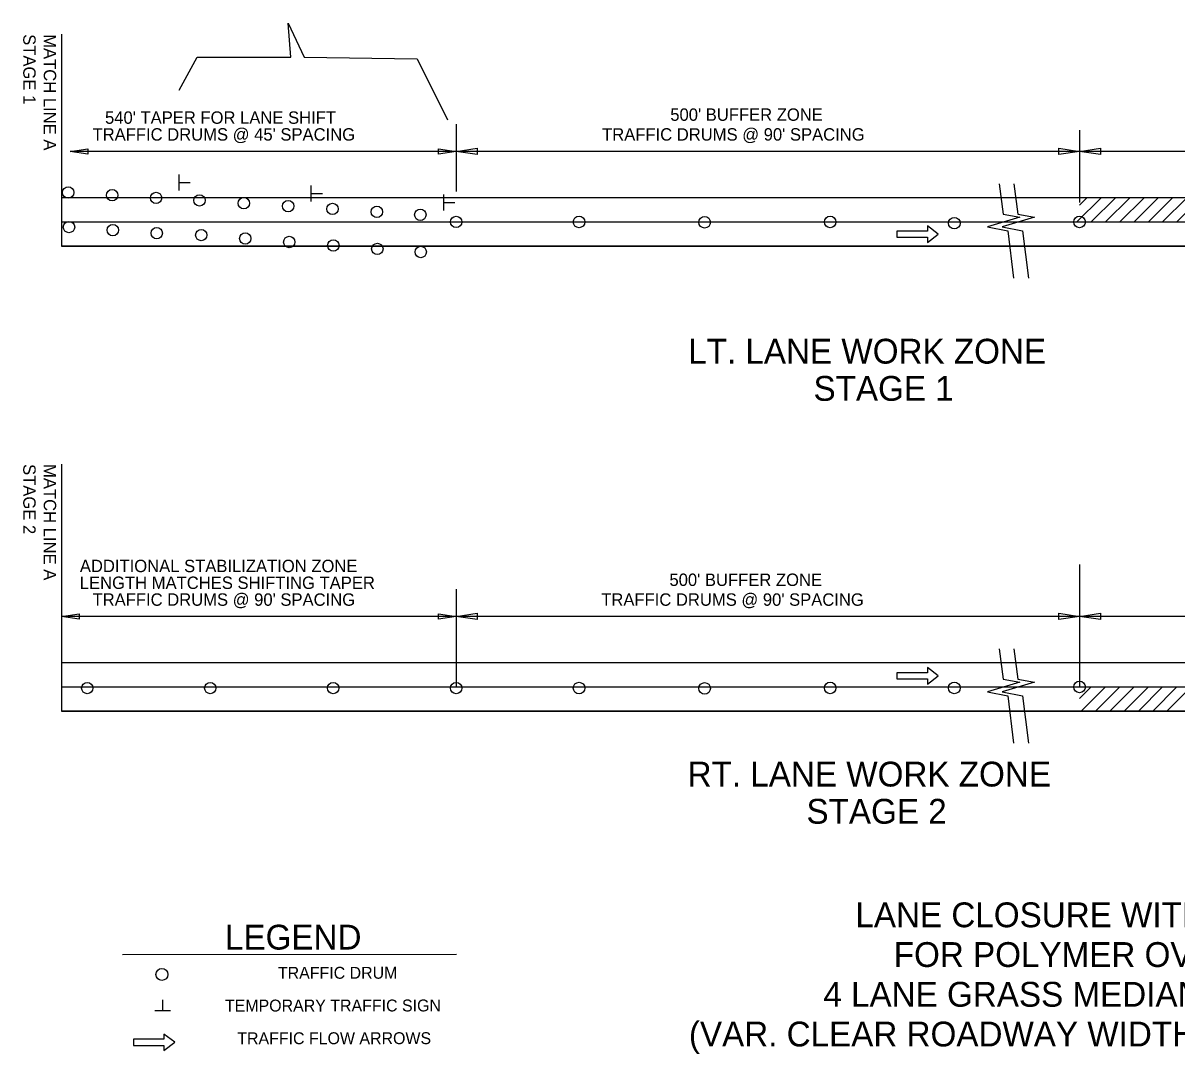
# Model space of a CAD drawing. Extents: x 1930579 to 1938222, y 596452 to 597559.
# Drawn here: x 1936678 to 1937236, y 596558 to 597056 of the extents above; entities that cross this region are included whole.
import ezdxf

# ---------------------------------------------------------------- set-up
doc = ezdxf.new("R2010")
doc.units = 0
for name, color, linetype in [('Default', 7, 'Continuous'), ('R_Border', 7, 'Continuous'), ('R_MOT', 7, 'Continuous'), ('R_Striping', 7, 'Continuous')]:
    doc.layers.add(name, color=color, linetype=linetype)

msp = doc.modelspace()

# ---------------------------------------------------------------- linework, layer by layer
at = {"layer": 'Default'}
for p, q in [((1936696.54, 597050.33), (1936696.54, 596947.87)), ((1936887.3, 597006.91), (1936887.3, 596974.28)), ((1937188.67, 597003.98), (1937188.67, 596968.94)), ((1936887.38, 596993.7), (1936897.44, 596995.21)), ((1936897.44, 596995.21), (1936897.44, 596992.19)), ((1937178.61, 596992.19), (1937178.61, 596995.21)), ((1937178.61, 596995.21), (1937188.67, 596993.7)), ((1937188.67, 596993.7), (1937198.73, 596995.21)), ((1937198.73, 596995.21), (1937198.73, 596992.19)), ((1936700.72, 596993.7), (1936709.21, 596994.97)), ((1936887.3, 596993.7), (1936700.72, 596993.7)), ((1936709.21, 596992.42), (1936700.72, 596993.7)), ((1936709.21, 596994.97), (1936709.21, 596992.42)), ((1936878.81, 596992.42), (1936878.81, 596994.97)), ((1936878.81, 596994.97), (1936887.3, 596993.7)), ((1936887.3, 596993.7), (1936878.81, 596992.42)), ((1937188.67, 596993.7), (1936887.3, 596993.7)), ((1936897.44, 596992.19), (1936887.38, 596993.7)), ((1937188.67, 596993.7), (1937178.61, 596992.19)), ((1937516.16, 596993.7), (1937188.67, 596993.7)), ((1937198.73, 596992.19), (1937188.67, 596993.7)), ((1936753.38, 596974.79), (1936753.38, 596982.58)), ((1936753.49, 596978.66), (1936758.81, 596978.66)), ((1936817.26, 596969.5), (1936817.26, 596977.29)), ((1936817.37, 596973.37), (1936822.69, 596973.37)), ((1936881.28, 596965.09), (1936881.28, 596972.88)), ((1937643.39, 596971.31), (1936696.54, 596971.31)), ((1936881.4, 596968.97), (1936886.72, 596968.97)), ((1937187.39, 596959.59), (1937199.11, 596971.31)), ((1937188.67, 596967.77), (1937192.21, 596971.31)), ((1937194.3, 596959.59), (1937206.02, 596971.31)), ((1937201.21, 596959.59), (1937212.92, 596971.31)), ((1937208.11, 596959.59), (1937219.83, 596971.31)), ((1937215.02, 596959.59), (1937226.73, 596971.31)), ((1937221.92, 596959.59), (1937233.64, 596971.31)), ((1937228.83, 596959.59), (1937240.55, 596971.31)), ((1937235.73, 596959.59), (1937247.45, 596971.31)), ((1936696.54, 596959.59), (1937643.39, 596959.59)), ((1936696.54, 596947.87), (1936970.48, 596947.87)), ((1937643.39, 596947.87), (1936696.54, 596947.87)), ((1936954.98, 596947.87), (1937223.6, 596947.87)), ((1937162.33, 596947.87), (1937188.46, 596947.87)), ((1937188.46, 596947.87), (1937335.53, 596947.87)), ((1936696.54, 596842.59), (1936696.54, 596723.17)), ((1937188.67, 596794.08), (1937188.67, 596744.24)), ((1937188.67, 596794.08), (1937188.67, 596744.24)), ((1936887.3, 596782.21), (1936887.3, 596734.89)), ((1937188.67, 596782.21), (1937188.67, 596734.89)), ((1936696.54, 596769), (1936705.03, 596770.27)), ((1936887.3, 596769), (1936696.54, 596769)), ((1936705.03, 596767.72), (1936696.54, 596769)), ((1936705.03, 596770.27), (1936705.03, 596767.72)), ((1936878.81, 596767.72), (1936878.81, 596770.27)), ((1936878.81, 596770.27), (1936887.3, 596769)), ((1936887.3, 596769), (1936878.81, 596767.72)), ((1937188.67, 596769), (1936887.3, 596769)), ((1936887.38, 596769), (1936897.44, 596770.51)), ((1936897.44, 596767.49), (1936887.38, 596769)), ((1936897.44, 596770.51), (1936897.44, 596767.49)), ((1937178.61, 596767.49), (1937178.61, 596770.51)), ((1937178.61, 596770.51), (1937188.67, 596769)), ((1937188.67, 596769), (1937178.61, 596767.49)), ((1937188.67, 596769), (1937198.73, 596770.51)), ((1937516.16, 596769), (1937188.67, 596769)), ((1937198.73, 596767.49), (1937188.67, 596769)), ((1937198.73, 596770.51), (1937198.73, 596767.49)), ((1937643.39, 596746.61), (1936696.54, 596746.61)), ((1936696.54, 596734.89), (1937643.39, 596734.89)), ((1937188.67, 596729.26), (1937194.3, 596734.89)), ((1937189.49, 596723.17), (1937201.21, 596734.89)), ((1937196.39, 596723.17), (1937208.11, 596734.89)), ((1937203.3, 596723.17), (1937215.02, 596734.89)), ((1937210.2, 596723.17), (1937221.92, 596734.89)), ((1937217.11, 596723.17), (1937228.83, 596734.89)), ((1937224.01, 596723.17), (1937235.73, 596734.89)), ((1937230.92, 596723.17), (1937242.64, 596734.89)), ((1936696.54, 596723.17), (1936970.48, 596723.17)), ((1937643.39, 596723.17), (1936696.54, 596723.17)), ((1936954.98, 596723.17), (1937223.6, 596723.17)), ((1937162.33, 596723.17), (1937188.46, 596723.17)), ((1937188.46, 596723.17), (1937335.53, 596723.17))]:
    msp.add_line(p, q, dxfattribs=at)
for points in [[(1937149.85, 596978.04), (1937151.68, 596963.38), (1937159.74, 596961.96), (1937144.09, 596957.22), (1937154.05, 596955.32), (1937156.8, 596932.48)], [(1937156.96, 596978.04), (1937158.79, 596963.38), (1937166.85, 596961.96), (1937151.2, 596957.22), (1937161.16, 596955.32), (1937163.91, 596932.48)], [(1937149.85, 596753.34), (1937151.68, 596738.68), (1937159.74, 596737.26), (1937144.09, 596732.52), (1937154.05, 596730.62), (1937156.8, 596707.78)], [(1937156.96, 596753.34), (1937158.79, 596738.68), (1937166.85, 596737.26), (1937151.2, 596732.52), (1937161.16, 596730.62), (1937163.91, 596707.78)]]:
    msp.add_lwpolyline(points, dxfattribs=at)
for centre, radius in [((1936699.79, 596973.82), 2.75), ((1936721.02, 596972.51), 2.75), ((1936742.25, 596971.19), 2.75), ((1936763.24, 596970.03), 2.75), ((1936784.68, 596968.65), 2.75), ((1936806.12, 596967.26), 2.75), ((1936827.55, 596965.88), 2.75), ((1936848.99, 596964.5), 2.75), ((1936869.99, 596963.06), 2.75), ((1936887.3, 596959.59), 2.75), ((1936946.73, 596959.59), 2.8), ((1937007.41, 596959.44), 2.8), ((1937068.09, 596959.59), 2.8), ((1937128.13, 596959.01), 2.8), ((1937188.67, 596959.59), 2.8), ((1936700.15, 596957.12), 2.75), ((1936721.36, 596955.65), 2.75), ((1936742.58, 596954.17), 2.75), ((1936764.09, 596953.25), 2.75), ((1936785.37, 596951.58), 2.75), ((1936806.65, 596949.9), 2.75), ((1936827.93, 596948.22), 2.75), ((1936849.21, 596946.54), 2.75), ((1936870.19, 596945.08), 2.75), ((1936709.01, 596734.35), 2.75), ((1936768.44, 596734.35), 2.75), ((1936827.87, 596734.35), 2.75), ((1936887.3, 596734.35), 2.75), ((1936946.73, 596734.35), 2.8), ((1937007.41, 596734.21), 2.8), ((1937068.09, 596734.41), 2.8), ((1937128.13, 596734.42), 2.8), ((1937188.67, 596734.89), 2.8), ((1936745.07, 596595.94), 2.88)]:
    msp.add_circle(centre, radius, dxfattribs=at)
at = {"layer": 'R_Border'}
for p, q in [((1936726.09, 596605.58), (1936887.49, 596605.69)), ((1936745.44, 596578.5), (1936745.44, 596583.74)), ((1936749.26, 596578.39), (1936741.58, 596578.39))]:
    msp.add_line(p, q, dxfattribs=at)
msp.add_lwpolyline([(1936753.38, 597023.29), (1936762.17, 597039.21), (1936807.32, 597039.21), (1936806.15, 597055.7), (1936813.77, 597039.21), (1936868.47, 597038.42), (1936883.18, 597008.99)], dxfattribs=at)
at = {"layer": 'R_MOT'}
msp.add_lwpolyline([(1936746.07, 596559.17), (1936751.26, 596563.18), (1936746.07, 596567.17), (1936746.07, 596564.67), (1936731.36, 596564.66), (1936731.36, 596561.66), (1936746.07, 596561.67)], close=True, dxfattribs=at)
at = {"layer": 'R_Striping'}
for points in [[(1937115.13, 596949.68), (1937120.32, 596953.68), (1937115.13, 596957.68), (1937115.13, 596955.18), (1937100.41, 596955.18), (1937100.41, 596952.18), (1937115.13, 596952.18)], [(1937115.13, 596736.23), (1937120.32, 596740.23), (1937115.13, 596744.23), (1937115.13, 596741.73), (1937100.41, 596741.73), (1937100.41, 596738.73), (1937115.13, 596738.73)]]:
    msp.add_lwpolyline(points, close=True, dxfattribs=at)

# ---------------------------------------------------------------- texts
at = {"layer": 'Default'}
for s, height, rotation, p in [('STAGE 1', 6, 270, (1936678.04, 597050.33)), ('MATCH LINE A ', 6, 270, (1936687.95, 597050.33)), ("540' TAPER FOR LANE SHIFT", 6, 360, (1936717.57, 597007.03)), ("500' BUFFER ZONE", 6, 360, (1936990.82, 597008.47)), ("TRAFFIC DRUMS @ 45' SPACING", 6, 360, (1936711.54, 596998.9)), ("TRAFFIC DRUMS @ 90' SPACING", 6, 360, (1936957.86, 596998.9)), ('LT. LANE WORK ZONE', 12, 360, (1936999.5, 596891.14)), ('STAGE 1', 12, 360, (1937060.06, 596873.16)), ('STAGE 2', 6, 270, (1936678.04, 596842.59)), ('MATCH LINE A ', 6, 270, (1936687.95, 596842.59)), ('ADDITIONAL STABILIZATION ZONE', 6, 360, (1936705.41, 596790.36)), ("500' BUFFER ZONE", 6, 360, (1936990.42, 596783.68)), ('LENGTH MATCHES SHIFTING TAPER', 6, 360, (1936705.38, 596782.23)), ("TRAFFIC DRUMS @ 90' SPACING", 6, 360, (1936711.54, 596774.11)), ("TRAFFIC DRUMS @ 90' SPACING", 6, 360, (1936957.45, 596774.11)), ('RT. LANE WORK ZONE', 12, 360, (1936999.21, 596686.77)), ('STAGE 2', 12, 360, (1937056.66, 596668.8)), ('LANE CLOSURE WITH TRAFFIC DRUMS', 12, 360, (1937080.32, 596618.76)), ('FOR POLYMER OVERLAY BRIDGES', 12, 360, (1937098.84, 596599.56)), ('4 LANE GRASS MEDIAN DIVIDED HIGHWAY', 12, 360, (1937064.83, 596580.36)), ('(VAR. CLEAR ROADWAY WIDTHS ON THE BRIDGE DECKS)', 12, 360, (1936999.82, 596561.16))]:
    msp.add_text(s, height=height, rotation=rotation, dxfattribs=at).set_placement(p)
at = {"layer": 'R_Border'}
for s, height, p in [('LEGEND', 12, (1936775.57, 596607.95)), ('TRAFFIC DRUM', 5.76, (1936801.15, 596593.84)), ('TEMPORARY TRAFFIC SIGN', 5.76, (1936775.54, 596578.01)), ('TRAFFIC FLOW ARROWS', 5.76, (1936781.5, 596562.21))]:
    msp.add_text(s, height=height, rotation=0.0388, dxfattribs=at).set_placement(p)

doc.saveas('drawing.dxf')
